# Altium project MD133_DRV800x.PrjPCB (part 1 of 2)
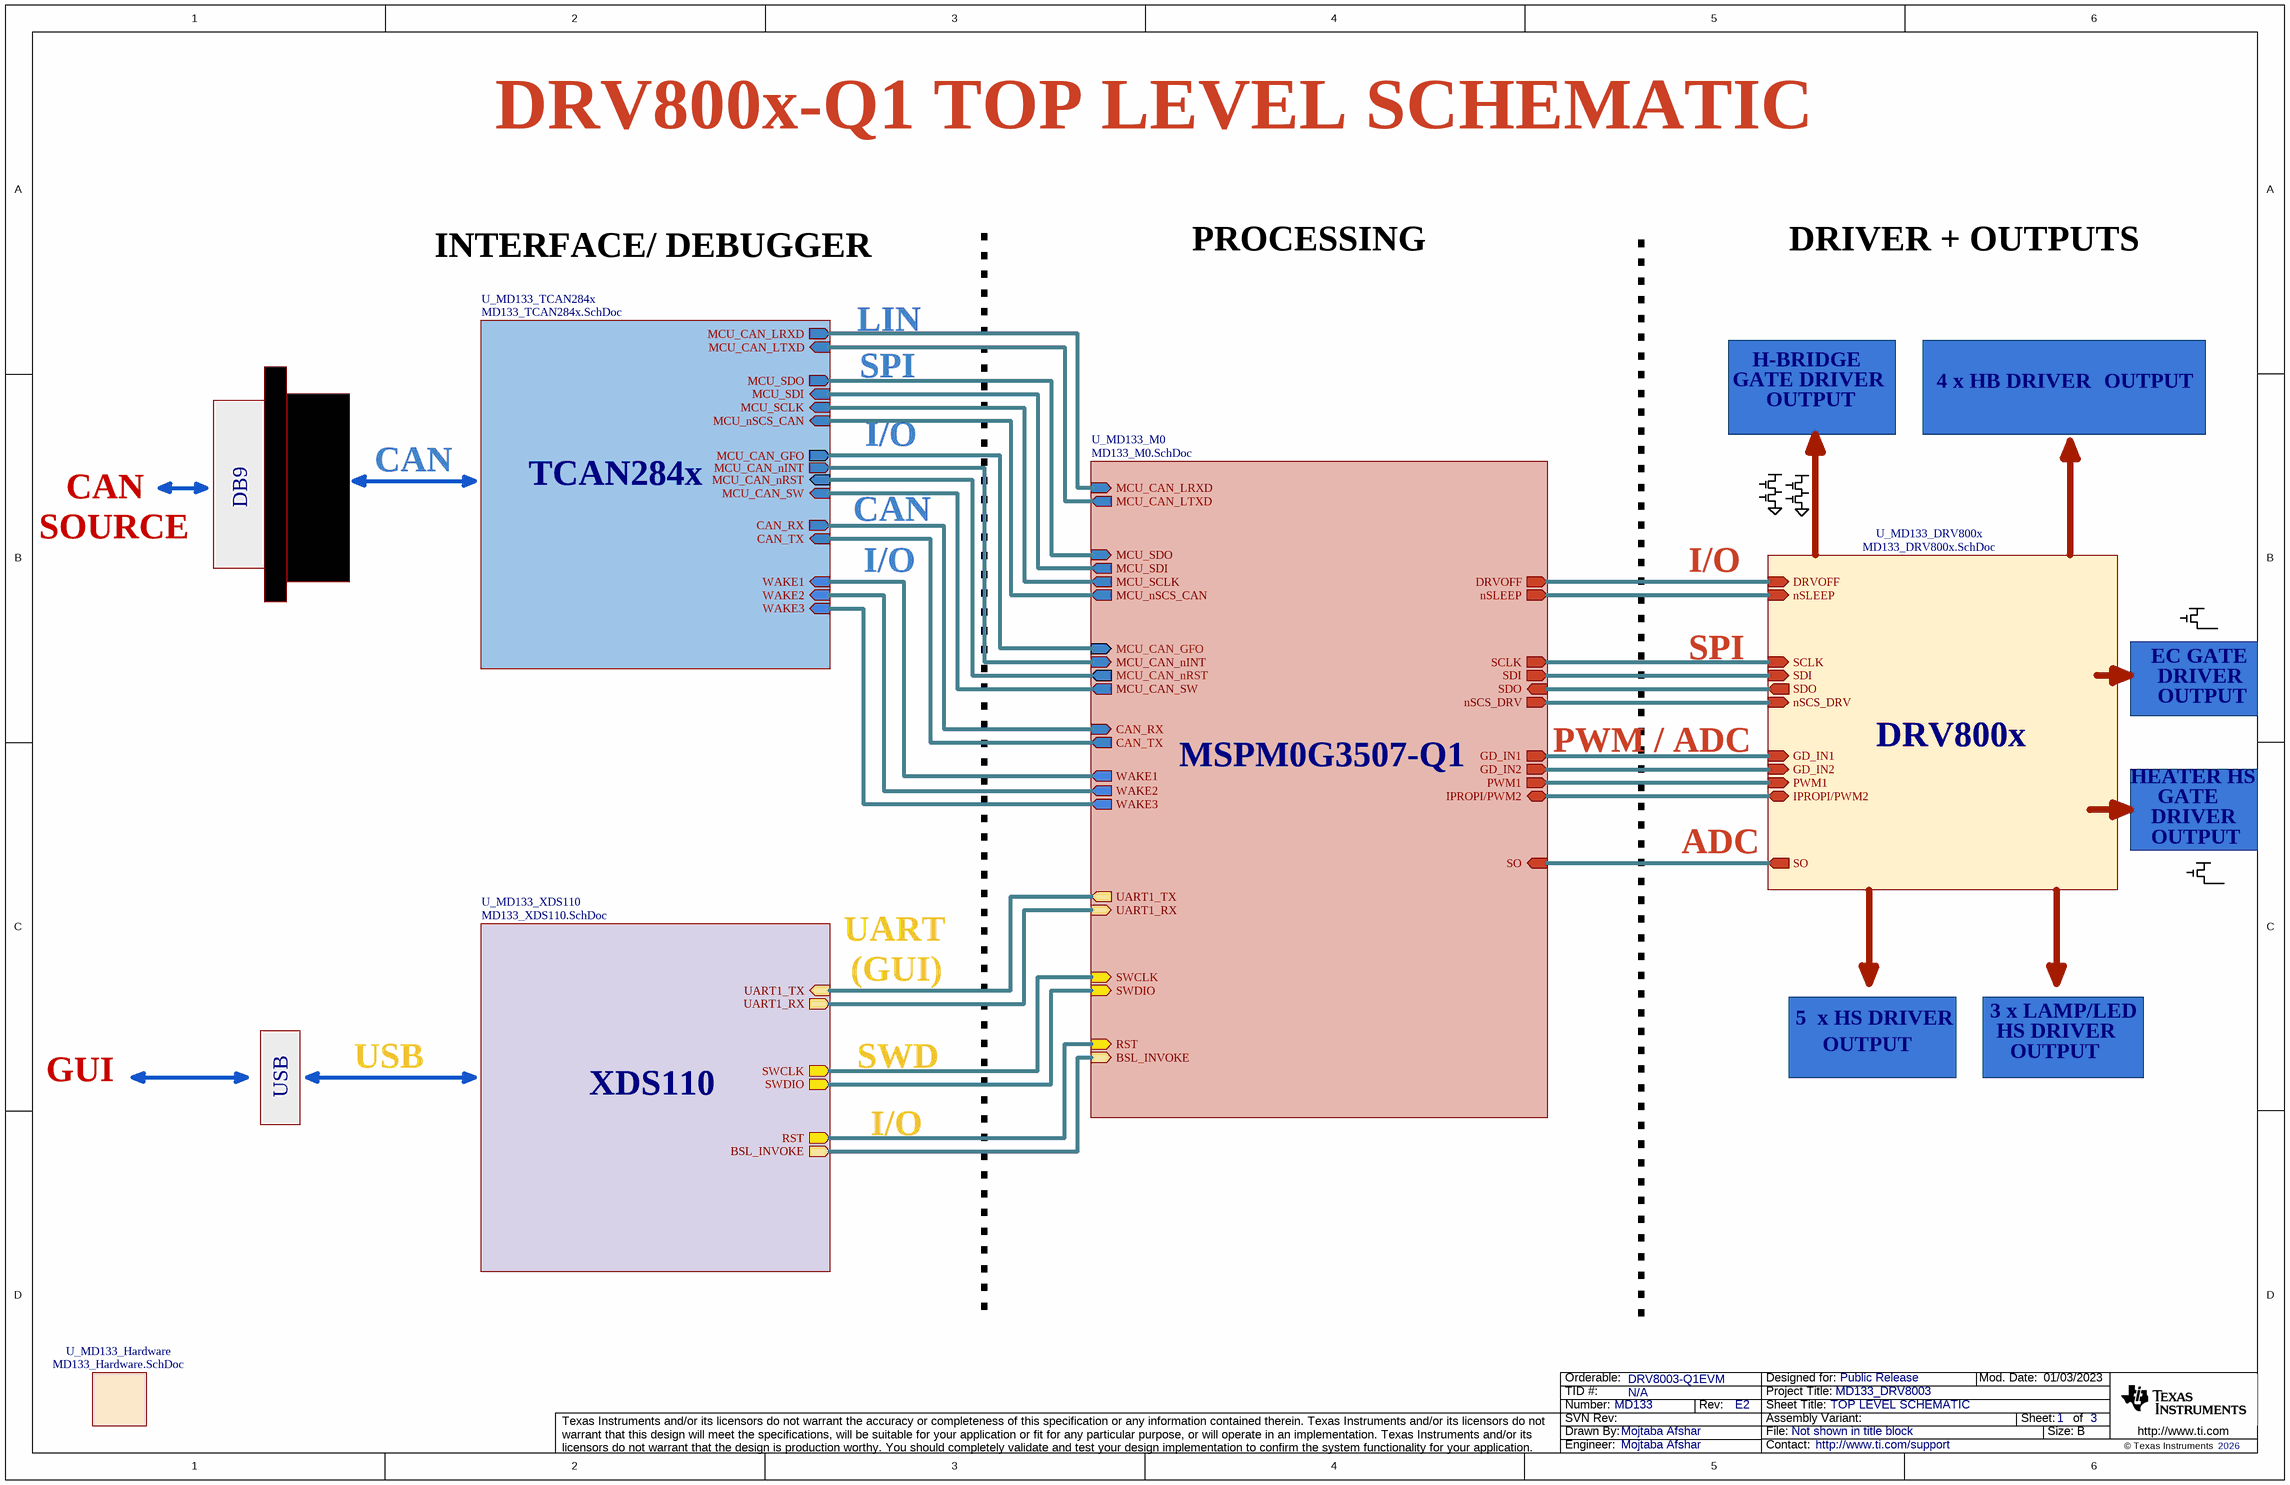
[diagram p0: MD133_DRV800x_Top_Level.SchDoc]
TID: N/A; TechSupport: http://www.ti.com/support; SCH_Rev: E2; PRJ_Title: MD133_DRV8003; PRJ_Number: MD133; PRJ_Engineer: Mojtaba Afshar; PRJ_Customer: Public Release; PCB_Rev: E2; PCB_Layout: Mojtaba Afshar; EVM_Orderable: DRV8003-Q1EVM; CopyrightYear: 2026
7 sheets, 317 parts. Net scope: flat (ports and power ports of the same name join across sheets).
Board file: MD133_DRV800x.PcbDoc
Sheets:
  MD133_DRV800x_Top_Level.SchDoc
    U_MD133_Hardware = MD133_Hardware.SchDoc
    U_MD133_XDS110 = MD133_XDS110.SchDoc
    U_MD133_M0 = MD133_M0.SchDoc
    U_MD133_TCAN284x = MD133_TCAN284x.SchDoc
    U_MD133_DRV800x = MD133_DRV800x.SchDoc
  Sheet1.SchDoc

## Sheet MD133_DRV800x_Top_Level.SchDoc: TOP LEVEL SCHEMATIC
size 431 x 279 mm; Date: Not shown in title block; ApprovedBy: Not shown in title block; CheckedBy: Not shown in title block; Author: Not shown in title block; CompanyName: Not shown in title block; DrawnBy: Mojtaba Afshar; Engineer: Not shown in title block; Organization: Not shown in title block; Address1: Not shown in title block; Address2: Not shown in title block; Address3: Not shown in title block; Address4: Not shown in title block; DocumentNumber: 2; Revision: Use project parameter SCH_Rev; SheetNumber: 1; SheetTotal: 3; PageSetup: Record=PageOptions¦CenterHorizontal=True¦CenterVertical=True¦PrintScale=1.00¦XCorrection=1.00¦YCorrection=1.00¦PrintKind=0¦BorderSize=5000000¦LeftOffset=0¦BottomOffset=0¦Orientation=2¦PaperLength=1000¦PaperWidth=1000¦Scale=100¦PaperSource=15¦PrintQuality=600¦MediaType=1¦DitherType=10¦PaperKind=Letter¦PrintScaleMode=1

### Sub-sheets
U_MD133_DRV800x = MD133_DRV800x.SchDoc: GD_IN1 (in), GD_IN2 (in), PWM1 (in), SDI (in), SDO (out), SCLK (in), IPROPI/PWM2 (bidir), DRVOFF (in), nSLEEP (in), SO (out), nSCS_DRV (in)
U_MD133_Hardware = MD133_Hardware.SchDoc: no entries
U_MD133_M0 = MD133_M0.SchDoc: SWDIO (in), SWCLK (in), GD_IN1 (out), GD_IN2 (out), PWM1 (out), SDI (out), SDO (in), SCLK (out), IPROPI/PWM2 (bidir), DRVOFF (out), nSLEEP (out), CAN_TX (out), CAN_RX (in), SO (in), RST (in), MCU_CAN_GFO (in), MCU_CAN_nRST (out), MCU_CAN_LTXD (out), MCU_CAN_LRXD (in), MCU_nSCS_CAN (out), MCU_SDO (in), MCU_SDI (out), MCU_SCLK (out), nSCS_DRV (out), MCU_CAN_SW (out), MCU_CAN_nINT (in), UART1_TX (out), UART1_RX (in), BSL_INVOKE (in), WAKE1 (out), WAKE2 (out), WAKE3 (out)
U_MD133_TCAN284x = MD133_TCAN284x.SchDoc: CAN_TX (in), CAN_RX (out), MCU_CAN_GFO (out), MCU_CAN_nRST (in), MCU_CAN_LTXD (in), MCU_CAN_LRXD (out), MCU_nSCS_CAN (in), MCU_SDO (out), MCU_SDI (in), MCU_SCLK (in), MCU_CAN_SW (in), MCU_CAN_nINT (out), WAKE1 (in), WAKE2 (in), WAKE3 (in)
U_MD133_XDS110 = MD133_XDS110.SchDoc: SWDIO (out), SWCLK (out), RST (out), UART1_RX (out), UART1_TX (in), BSL_INVOKE (out)

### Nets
(unnamed): sheet U_MD133_XDS110/SWDIO, sheet U_MD133_M0/SWDIO
(unnamed): sheet U_MD133_XDS110/SWCLK, sheet U_MD133_M0/SWCLK  [a separate net that carries the same name]
(unnamed): sheet U_MD133_XDS110/RST, sheet U_MD133_M0/RST  [a separate net that carries the same name]
(unnamed): sheet U_MD133_XDS110/UART1_RX, sheet U_MD133_M0/UART1_RX  [a separate net that carries the same name]
(unnamed): sheet U_MD133_XDS110/UART1_TX, sheet U_MD133_M0/UART1_TX  [a separate net that carries the same name]
(unnamed): sheet U_MD133_XDS110/BSL_INVOKE, sheet U_MD133_M0/BSL_INVOKE  [a separate net that carries the same name]
(unnamed): sheet U_MD133_M0/GD_IN1, sheet U_MD133_DRV800x/GD_IN1  [a separate net that carries the same name]
(unnamed): sheet U_MD133_M0/GD_IN2, sheet U_MD133_DRV800x/GD_IN2  [a separate net that carries the same name]
(unnamed): sheet U_MD133_M0/PWM1, sheet U_MD133_DRV800x/PWM1  [a separate net that carries the same name]
(unnamed): sheet U_MD133_M0/SDI, sheet U_MD133_DRV800x/SDI  [a separate net that carries the same name]
(unnamed): sheet U_MD133_M0/SDO, sheet U_MD133_DRV800x/SDO  [a separate net that carries the same name]
(unnamed): sheet U_MD133_M0/SCLK, sheet U_MD133_DRV800x/SCLK  [a separate net that carries the same name]
(unnamed): sheet U_MD133_M0/IPROPI/PWM2, sheet U_MD133_DRV800x/IPROPI/PWM2  [a separate net that carries the same name]
(unnamed): sheet U_MD133_M0/DRVOFF, sheet U_MD133_DRV800x/DRVOFF  [a separate net that carries the same name]
(unnamed): sheet U_MD133_M0/nSLEEP, sheet U_MD133_DRV800x/nSLEEP  [a separate net that carries the same name]
(unnamed): sheet U_MD133_M0/CAN_TX, sheet U_MD133_TCAN284x/CAN_TX  [a separate net that carries the same name]
(unnamed): sheet U_MD133_M0/CAN_RX, sheet U_MD133_TCAN284x/CAN_RX  [a separate net that carries the same name]
(unnamed): sheet U_MD133_M0/SO, sheet U_MD133_DRV800x/SO  [a separate net that carries the same name]
(unnamed): sheet U_MD133_M0/MCU_CAN_GFO, sheet U_MD133_TCAN284x/MCU_CAN_GFO  [a separate net that carries the same name]
(unnamed): sheet U_MD133_M0/MCU_CAN_nRST, sheet U_MD133_TCAN284x/MCU_CAN_nRST  [a separate net that carries the same name]
(unnamed): sheet U_MD133_M0/MCU_CAN_LTXD, sheet U_MD133_TCAN284x/MCU_CAN_LTXD  [a separate net that carries the same name]
(unnamed): sheet U_MD133_M0/MCU_CAN_LRXD, sheet U_MD133_TCAN284x/MCU_CAN_LRXD  [a separate net that carries the same name]
(unnamed): sheet U_MD133_M0/MCU_nSCS_CAN, sheet U_MD133_TCAN284x/MCU_nSCS_CAN  [a separate net that carries the same name]
(unnamed): sheet U_MD133_M0/MCU_SDO, sheet U_MD133_TCAN284x/MCU_SDO  [a separate net that carries the same name]
(unnamed): sheet U_MD133_M0/MCU_SDI, sheet U_MD133_TCAN284x/MCU_SDI  [a separate net that carries the same name]
(unnamed): sheet U_MD133_M0/MCU_SCLK, sheet U_MD133_TCAN284x/MCU_SCLK  [a separate net that carries the same name]
(unnamed): sheet U_MD133_M0/nSCS_DRV, sheet U_MD133_DRV800x/nSCS_DRV  [a separate net that carries the same name]
(unnamed): sheet U_MD133_M0/MCU_CAN_SW, sheet U_MD133_TCAN284x/MCU_CAN_SW  [a separate net that carries the same name]
(unnamed): sheet U_MD133_M0/MCU_CAN_nINT, sheet U_MD133_TCAN284x/MCU_CAN_nINT  [a separate net that carries the same name]
(unnamed): sheet U_MD133_M0/WAKE1, sheet U_MD133_TCAN284x/WAKE1  [a separate net that carries the same name]
(unnamed): sheet U_MD133_M0/WAKE2, sheet U_MD133_TCAN284x/WAKE2  [a separate net that carries the same name]
(unnamed): sheet U_MD133_M0/WAKE3, sheet U_MD133_TCAN284x/WAKE3  [a separate net that carries the same name]

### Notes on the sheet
- DRV800x-Q1 TOP LEVEL SCHEMATIC
- INTERFACE/ DEBUGGER
- PROCESSING
- DRIVER + OUTPUTS
- LIN
- H-BRIDGE
- SPI
- GATE DRIVER
- OUTPUT
- 4 x HB DRIVER
- CAN
- TCAN284x
- I/O
- SOURCE
- DB9
- EC GATE
- DRIVER
- PWM / ADC
- DRV800x
- MSPM0G3507-Q1
- HEATER HS
- GATE
- ADC
- UART
- (GUI)
- 5  x HS DRIVER
- 3 x LAMP/LED
- GUI
- USB
- XDS110
- SWD
- HS DRIVER

## Sheet MD133_Hardware.SchDoc: HARDWARE
size 431 x 279 mm; Date: Not shown in title block; ApprovedBy: Not shown in title block; CheckedBy: Not shown in title block; Author: Not shown in title block; CompanyName: Not shown in title block; DrawnBy: Mojtaba Afshar; Engineer: Not shown in title block; Organization: Not shown in title block; Address1: Not shown in title block; Address2: Not shown in title block; Address3: Not shown in title block; Address4: Not shown in title block; DocumentNumber: 3; Revision: Use project parameter SCH_Rev; SheetNumber: 6; SheetTotal: 2; PageSetup: Record=PageOptions¦CenterHorizontal=True¦CenterVertical=True¦PrintScale=1.00¦XCorrection=1.00¦YCorrection=1.00¦PrintKind=0¦BorderSize=5000000¦LeftOffset=0¦BottomOffset=0¦Orientation=2¦PaperLength=1000¦PaperWidth=1000¦Scale=100¦PaperSource=15¦PrintQuality=600¦MediaType=1¦DitherType=10¦PaperKind=Letter¦PrintScaleMode=1
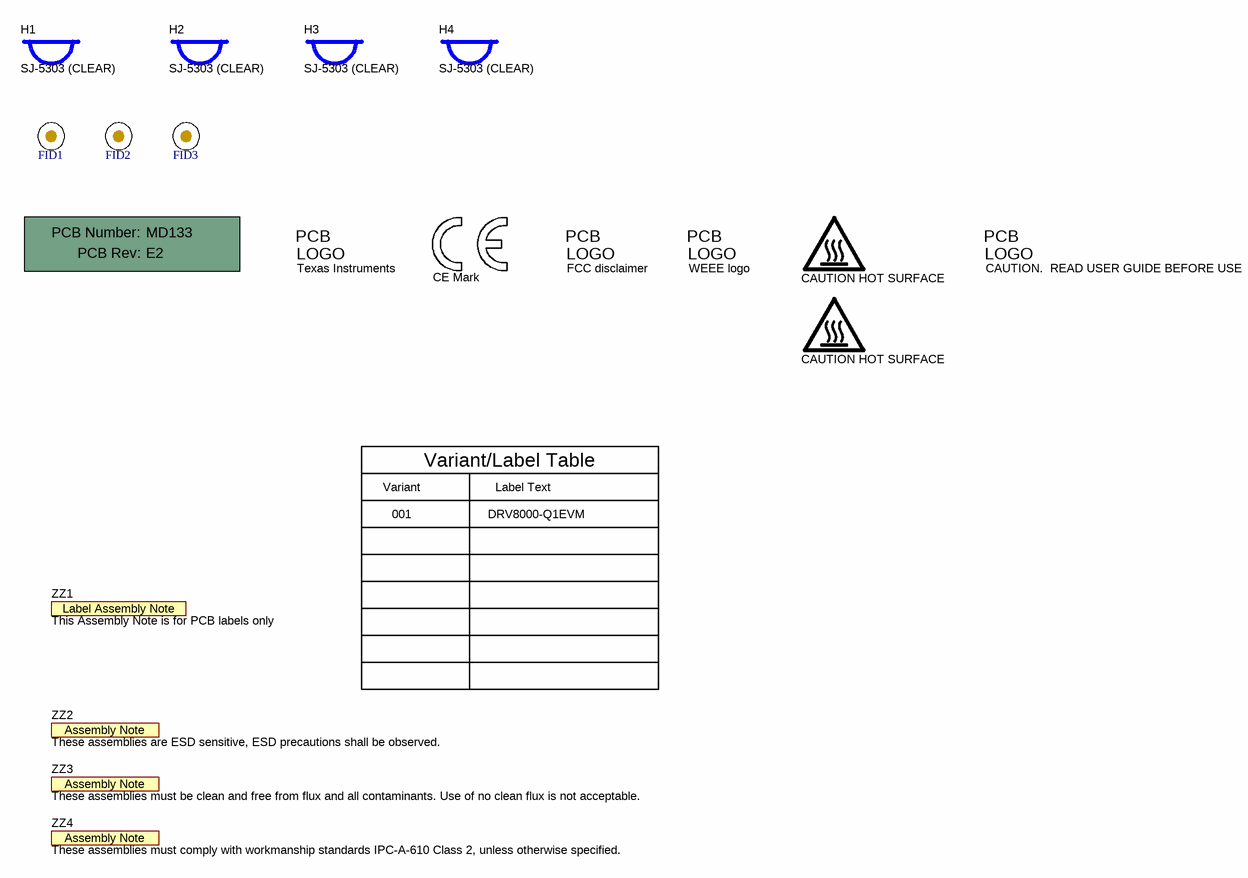
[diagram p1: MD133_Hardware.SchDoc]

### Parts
!PCB1  Printed Circuit Board  (value not drawn)  (mechanical)
FID1  Fiducial  [Fiducial10-20]  (value not drawn)
FID2  Fiducial  [Fiducial10-20]  (value not drawn)
FID3  Fiducial  [Fiducial10-20]  (value not drawn)
H1  SJ-5303 (CLEAR)  [Bumpon_SJ5003Transparent]
H2  SJ-5303 (CLEAR)  [Bumpon_SJ5003Transparent]
H3  SJ-5303 (CLEAR)  [Bumpon_SJ5003Transparent]
H4  SJ-5303 (CLEAR)  [Bumpon_SJ5003Transparent]
Logo1  CE Mark  [CE_Mark_5mm]  (no BOM)
Logo2  Texas Instruments  [TI_Stacked_Overlay_Small]  (no BOM)
Logo3  FCC disclaimer  [FCC_disclaimer]  (no BOM)
Logo4  WEEE logo  [WEEE_Minimum]  (no BOM)
LOGO5  CAUTION HOT SURFACE  [IEC_HotSurface_Small]  (no BOM)
Logo6  CAUTION.  READ USER GUIDE BEFORE USE  [IEC_Caution_Small]  (no BOM)
LOGO7  CAUTION HOT SURFACE  [IEC_HotSurface_Small]  (no BOM)
ZZ1  This Assembly Note is for PCB labels only  [AssemblyNoteLabel]  (no BOM)
ZZ2  These assemblies are ESD sensitive, ESD precautions shall be observed.  [AssemblyNote]  (no BOM)
ZZ3  These assemblies must be clean and free from flux and all contaminants. Use of no clean flux is not acceptable.  [AssemblyNote]  (no BOM)
ZZ4  These assemblies must comply with workmanship standards IPC-A-610 Class 2, unless otherwise specified.  [AssemblyNote]  (no BOM)

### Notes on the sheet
- Variant
- Variant/Label Table
- Label Text
- 001
- DRV8000-Q1EVM

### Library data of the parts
!PCB1 = CMP-0003618-2: Manufacturer: Any; PartNumber: MD133
FID1-FID3 = CMP-0077181-1: Fiducial mark.  There is nothing to buy or mount.
H1-H4 = CMP-0003620-1: Bumpon, Hemisphere, 0.44 X 0.20, Clear; Manufacturer: 3M
Logo1 = CMP-0074844-1: SymbolCreator: a0412235
Logo2 = CMP-0074838-1: Texas Instrument Corporate Signature; SymbolCreator: a0412235; Lib Reference: TI_Logo
Logo3 = CMP-0074847-1: FCC_disclaimer
Logo4 = CMP-0074769-3: Manufacturer: Texas Instruments; AEC Category: Q200; CompType: IC
LOGO5 LOGO7 = CMP-0074837-2: IEC 61010-1 Hot Surface Warning; Manufacturer: Texas Instruments; SymbolCreator: a0412235; CompType: IC; AEC Category: Q200
Logo6 = CMP-0074836-1: IEC 61010-1 Caution Warning; SymbolCreator: a0412235; Lib Reference: IEC_Caution
ZZ1 = CMP-0003616-3
ZZ2 = CMP-0077236-1
ZZ3 = CMP-0077237-1
ZZ4 = CMP-0077238-1

## Sheet MD133_XDS110.SchDoc: XDS110
size 431 x 279 mm; Date: Not shown in title block; ApprovedBy: Not shown in title block; CheckedBy: Not shown in title block; Author: Not shown in title block; CompanyName: Not shown in title block; DrawnBy: Mojtaba Afshar; Engineer: Not shown in title block; Organization: Not shown in title block; Address1: Not shown in title block; Address2: Not shown in title block; Address3: Not shown in title block; Address4: Not shown in title block; DocumentNumber: 2; Revision: Use project parameter SCH_Rev; SheetNumber: 2; SheetTotal: 2; PageSetup: Record=PageOptions¦CenterHorizontal=True¦CenterVertical=True¦PrintScale=1.00¦XCorrection=1.00¦YCorrection=1.00¦PrintKind=0¦BorderSize=5000000¦LeftOffset=0¦BottomOffset=0¦Orientation=2¦PaperLength=1000¦PaperWidth=1000¦Scale=100¦PaperSource=15¦PrintQuality=600¦MediaType=1¦DitherType=10¦PaperKind=Letter¦PrintScaleMode=1
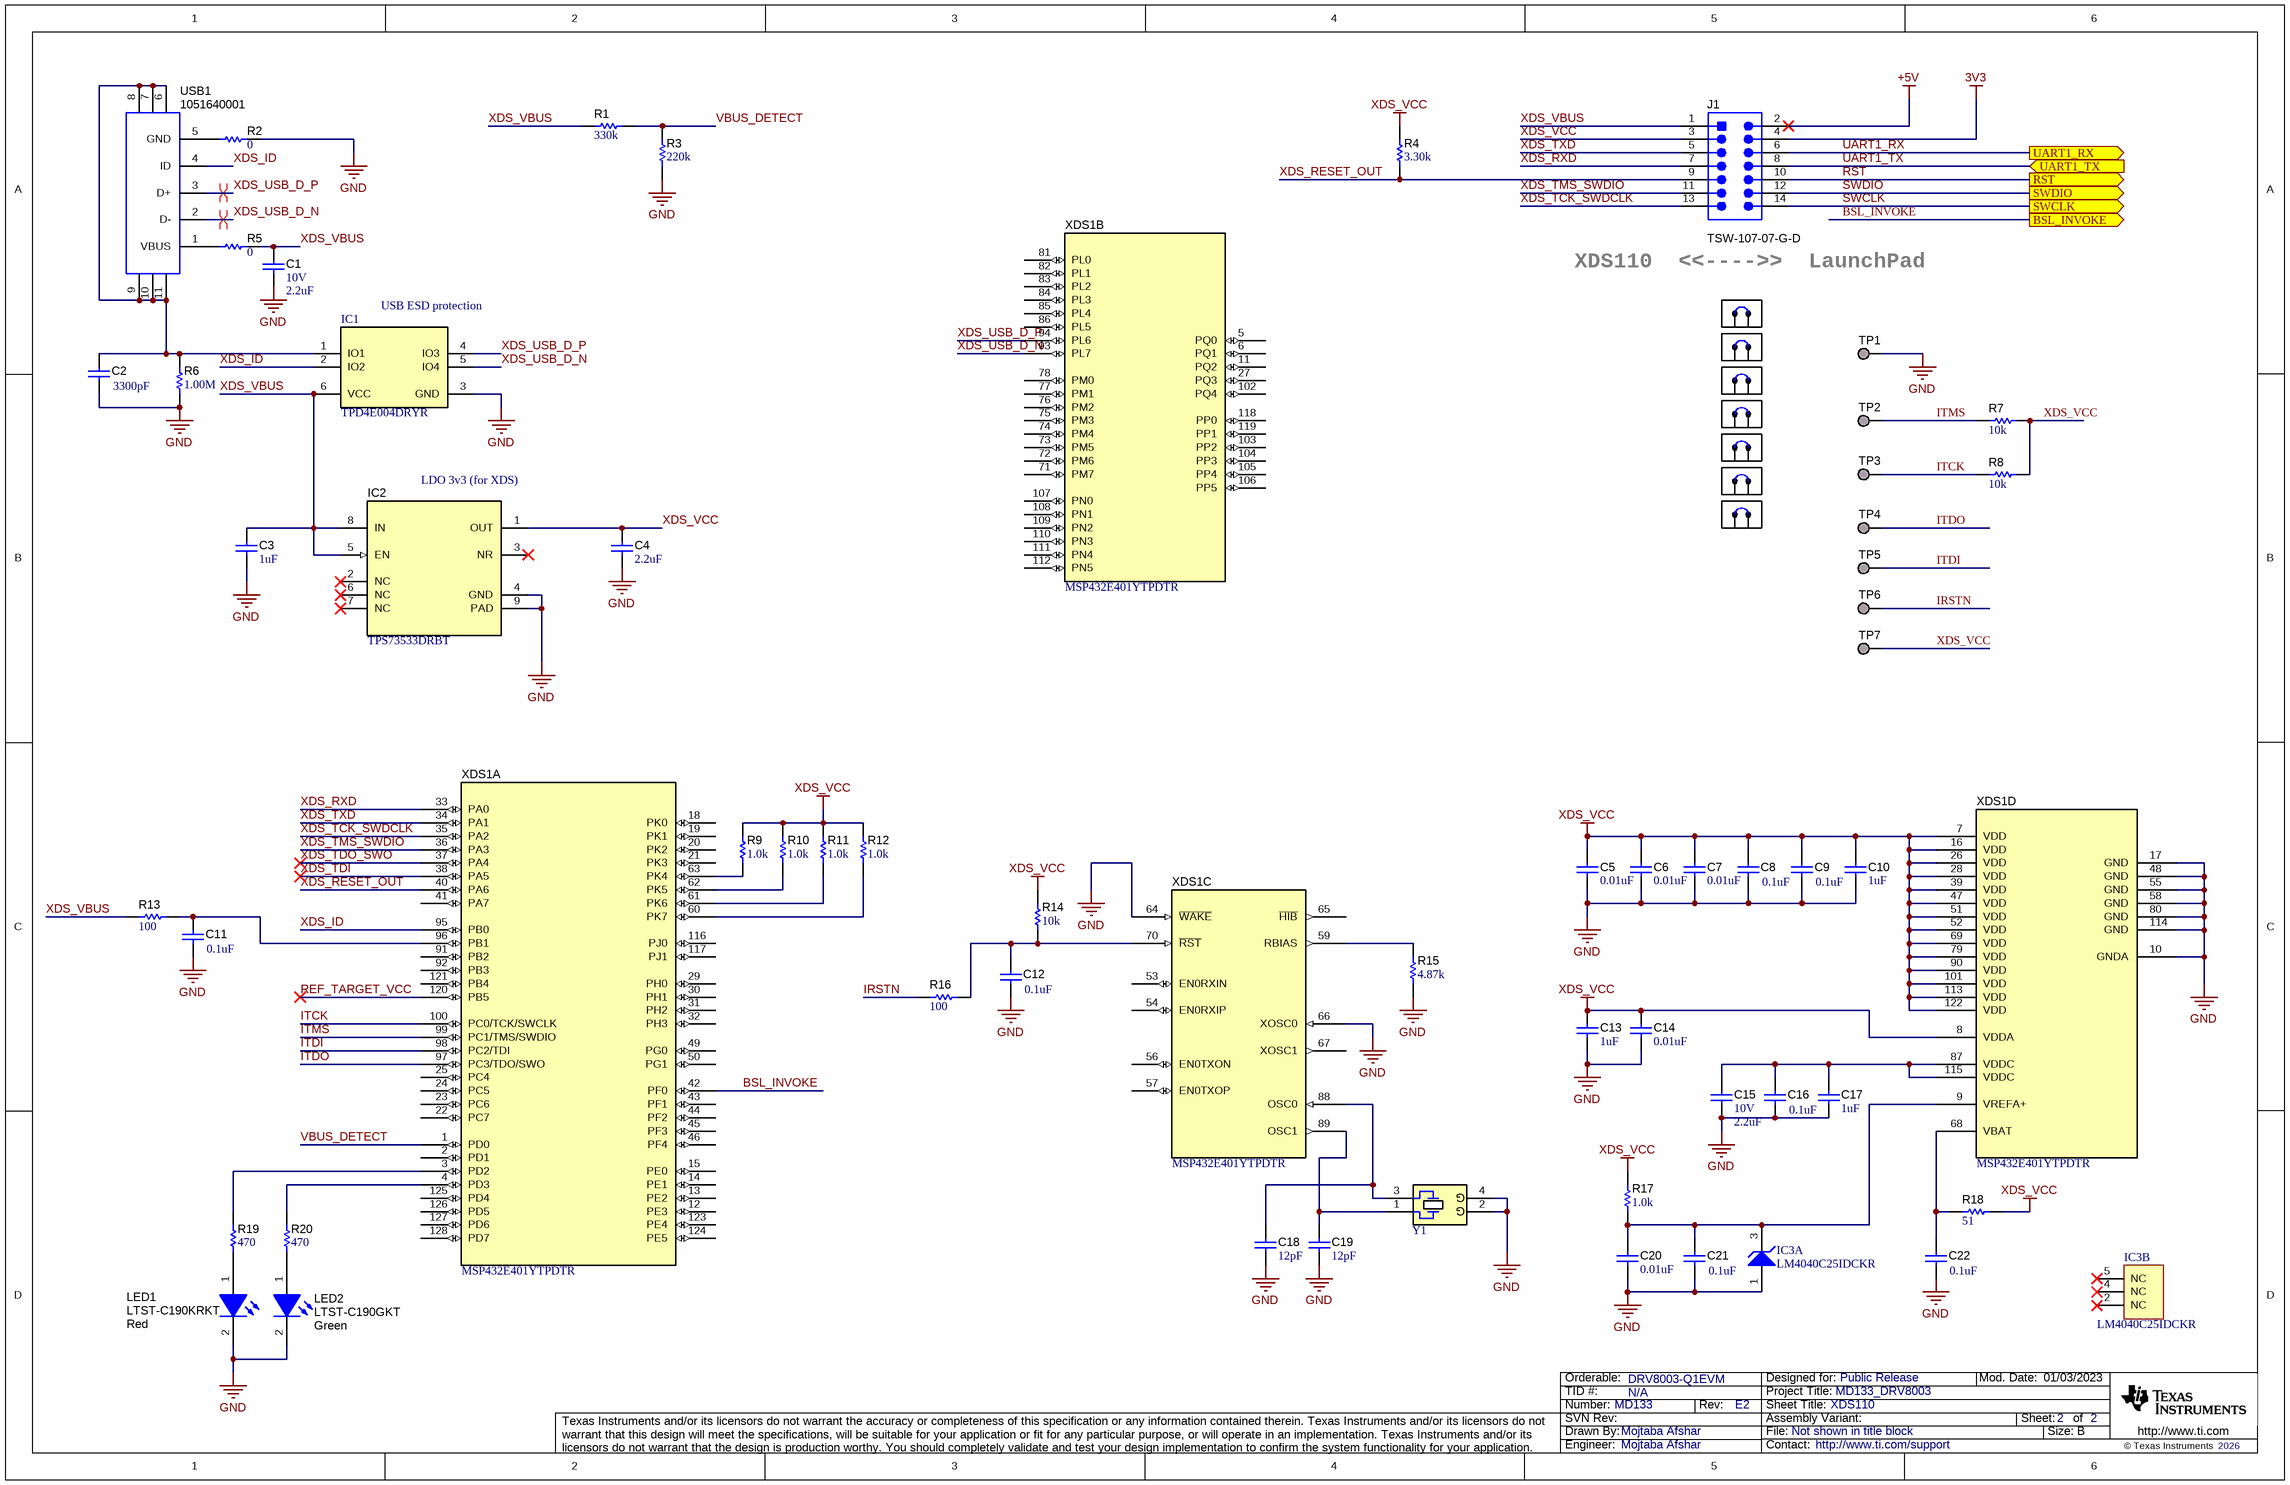
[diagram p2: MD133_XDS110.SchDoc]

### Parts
C1  VDC_V: 10V  ValueDisplayed: 2.2uF  [0603]  (hidden comment: C0603C225K8PACTU)
C2  ValueDisplayed: 3300pF  [0402]  (hidden comment: GRM155R71H332KA01D)
C3  ValueDisplayed: 1uF  [0402]  (hidden comment: C1005X5R1E105K050BC)
C4  ValueDisplayed: 2.2uF  [0402]  (hidden comment: CL05A225KQ5NNNC)
C5  ValueDisplayed: 0.01uF  [0402]  (hidden comment: GRM155R71E103KA01D)
C6  ValueDisplayed: 0.01uF  [0402]  (hidden comment: GRM155R71E103KA01D)
C7  ValueDisplayed: 0.01uF  [0402]  (hidden comment: GRM155R71E103KA01D)
C8  ValueDisplayed: 0.1uF  [0402]  (hidden comment: GRM155R70J104KA01D)
C9  ValueDisplayed: 0.1uF  [0402]  (hidden comment: GRM155R70J104KA01D)
C10  ValueDisplayed: 1uF  [0402]  (hidden comment: C1005X5R1E105K050BC)
C11  ValueDisplayed: 0.1uF  [0402]  (hidden comment: GRM155R70J104KA01D)
C12  ValueDisplayed: 0.1uF  [0402]  (hidden comment: GRM155R70J104KA01D)
C13  ValueDisplayed: 1uF  [0402]  (hidden comment: C1005X5R1E105K050BC)
C14  ValueDisplayed: 0.01uF  [0402]  (hidden comment: GRM155R71E103KA01D)
C15  VDC_V: 10V  ValueDisplayed: 2.2uF  [0603]  (hidden comment: C0603C225K8PACTU)
C16  ValueDisplayed: 0.1uF  [0402]  (hidden comment: GRM155R70J104KA01D)
C17  ValueDisplayed: 1uF  [0402]  (hidden comment: C1005X5R1E105K050BC)
C18  ValueDisplayed: 12pF  [0402]  (hidden comment: GRM1555C1H120JA01D)
C19  ValueDisplayed: 12pF  [0402]  (hidden comment: GRM1555C1H120JA01D)
C20  ValueDisplayed: 0.01uF  [0402]  (hidden comment: GRM155R71E103KA01D)
C21  ValueDisplayed: 0.1uF  [0402]  (hidden comment: GRM155R70J104KA01D)
C22  ValueDisplayed: 0.1uF  [0402]  (hidden comment: GRM155R70J104KA01D)
IC1  TPD4E004DRYR  [DRY0006A]
IC2  TPS73533DRBT  [DRB0008A]
IC3  LM4040C25IDCKR  [DCK0005A_N]  (parts A,B of 2)
J1  TSW-107-07-G-D  [TSW-107-07-X-D]
LED1  LTST-C190KRKT  value Red  [LED_LTST-C190_Red]
LED2  LTST-C190GKT  value Green  [LED_LTST-C190]
R1  ValueDisplayed: 330k  [0402]  (hidden comment: RC0402FR-07330KL)
R2  ValueDisplayed: 0  [0603]  (hidden comment: RC0603JR-070RL)
R3  ValueDisplayed: 220k  [0402]  (hidden comment: RC0402FR-07220KL)
R4  ValueDisplayed: 3.30k  [0402]  (hidden comment: ERJ-2RKF3301X)
R5  ValueDisplayed: 0  [0603]  (hidden comment: RC0603JR-070RL)
R6  ValueDisplayed: 1.00M  [0402]  (hidden comment: CRCW04021M00FKED)
R7  ValueDisplayed: 10k  [0402]  (hidden comment: CRCW040210K0JNED)
R8  ValueDisplayed: 10k  [0402]  (hidden comment: CRCW040210K0JNED)
R9  ValueDisplayed: 1.0k  [0402]  (hidden comment: CRCW04021K00JNED)
R10  ValueDisplayed: 1.0k  [0402]  (hidden comment: CRCW04021K00JNED)
R11  ValueDisplayed: 1.0k  [0402]  (hidden comment: CRCW04021K00JNED)
R12  ValueDisplayed: 1.0k  [0402]  (hidden comment: CRCW04021K00JNED)
R13  ValueDisplayed: 100  [0402]  (hidden comment: CRCW0402100RJNED)
R14  ValueDisplayed: 10k  [0402]  (hidden comment: CRCW040210K0JNED)
R15  ValueDisplayed: 4.87k  [0402]  (hidden comment: CRCW04024K87FKED)
R16  ValueDisplayed: 100  [0402]  (hidden comment: CRCW0402100RJNED)
R17  ValueDisplayed: 1.0k  [0402]  (hidden comment: CRCW04021K00JNED)
R18  ValueDisplayed: 51  [0402]  (hidden comment: CRCW040251R0JNED)
R19  ValueDisplayed: 470  [0402]  (hidden comment: CRCW0402470RJNED)
R20  ValueDisplayed: 470  [0402]  (hidden comment: CRCW0402470RJNED)
SH-J14  60900213421  [Wurth_60900213421]  (value not drawn)
SH-J15  60900213421  [Wurth_60900213421]  (value not drawn)
SH-J16  60900213421  [Wurth_60900213421]  (value not drawn)
SH-J17  60900213421  [Wurth_60900213421]  (value not drawn)
SH-J18  60900213421  [Wurth_60900213421]  (value not drawn)
SH-J19  60900213421  [Wurth_60900213421]  (value not drawn)
SH-J20  60900213421  [Wurth_60900213421]  (value not drawn)
TP1  TESTPOINT  [TP_SM_1MM]  (value not drawn)  (no BOM)
TP2  TESTPOINT  [TP_SM_1MM]  (value not drawn)  (no BOM)
TP3  TESTPOINT  [TP_SM_1MM]  (value not drawn)  (no BOM)
TP4  TESTPOINT  [TP_SM_1MM]  (value not drawn)  (no BOM)
TP5  TESTPOINT  [TP_SM_1MM]  (value not drawn)  (no BOM)
TP6  TESTPOINT  [TP_SM_1MM]  (value not drawn)  (no BOM)
TP7  TESTPOINT  [TP_SM_1MM]  (value not drawn)  (no BOM)
USB1  1051640001  [Molex_1051640001]
XDS1  MSP432E401YTPDTR  [PDT0128A]  (parts A,B,C,D of 4)
Y1  NX3225GA-16.000M-STD-CRG-1  [NDK_NX3225GA]  (value not drawn)

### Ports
BSL_INVOKE (out), RST (out), SWCLK (out), SWDIO (out), UART1_RX (out), UART1_TX (in)

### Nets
3V3: J1.4
+5V: J1.2
GND: C1.2 C2.2 C3.2 C4.2 C5.2 C6.2 C7.2 C8.2 C9.2 C10.2 C11.2 C12.2 C13.2 C14.2 C15.2 C16.2 C17.2 C18.2 C19.2 C20.2 C21.2 C22.2 IC1.3(GND) IC2.4(GND) IC2.9(PAD) IC3.1(ANODE) LED1.2(K) LED2.2(K) R2.2 R3.1 R6.1 R15.1 TP1.1 XDS1.10(GNDA) XDS1.17(GND) XDS1.48(GND) XDS1.55(GND) XDS1.58(GND) XDS1.64(~{WAKE}) XDS1.66(XOSC0) XDS1.80(GND) XDS1.114(GND) Y1.2(GND) Y1.4(GND)
XDS_VCC: C4.1 C5.1 C6.1 C7.1 C8.1 C9.1 C10.1 C13.1 C14.1 IC2.1(OUT) J1.3 R4.2 R7.1 R8.1 R9.2 R10.2 R11.2 R12.2 R14.2 R17.2 R18.2 TP7.1 XDS1.7(VDD) XDS1.8(VDDA) XDS1.16(VDD) XDS1.26(VDD) XDS1.28(VDD) XDS1.39(VDD) XDS1.47(VDD) XDS1.51(VDD) XDS1.52(VDD) XDS1.69(VDD) XDS1.79(VDD) XDS1.90(VDD) XDS1.101(VDD) XDS1.113(VDD) XDS1.122(VDD)
BSL_INVOKE: XDS1.42(PF0) ; port BSL_INVOKE
IRSTN: R16.1 TP6.1
ITCK: R8.2 TP3.1 XDS1.100(PC0/TCK/SWCLK)
ITDI: TP5.1 XDS1.98(PC2/TDI)
ITDO: TP4.1 XDS1.97(PC3/TDO/SWO)
ITMS: R7.2 TP2.1 XDS1.99(PC1/TMS/SWDIO)
REF_TARGET_VCC: XDS1.120(PB5)
RST: J1.10 ; port RST
SWCLK: J1.14 ; port SWCLK
SWDIO: J1.12 ; port SWDIO
UART1_RX: J1.6 ; port UART1_RX
UART1_TX: J1.8 ; port UART1_TX
VBUS_DETECT: R1.2 R3.2 XDS1.1(PD0)
XDS_ID: IC1.2(IO2) USB1.4(ID) XDS1.95(PB0)
XDS_RESET_OUT: J1.9 R4.1 XDS1.40(PA6)
XDS_RXD: J1.7 XDS1.33(PA0)
XDS_TCK_SWDCLK: J1.13 XDS1.35(PA2)
XDS_TDI: XDS1.38(PA5)
XDS_TDO_SWO: XDS1.37(PA4)
XDS_TMS_SWDIO: J1.11 XDS1.36(PA3)
XDS_TXD: J1.5 XDS1.34(PA1)
XDS_USB_D_N: IC1.5(IO4) USB1.2(D-) XDS1.93(PL7)
XDS_USB_D_P: IC1.4(IO3) USB1.3(D+) XDS1.94(PL6)
XDS_VBUS: C1.1 C3.1 IC1.6(VCC) IC2.5(EN) IC2.8(IN) J1.1 R1.1 R5.2 R13.1
NetC2_1: C2.1 IC1.1(IO1) R6.2 USB1.6 USB1.7 USB1.8 USB1.9 USB1.10 USB1.11
NetC11_1: C11.1 R13.2 XDS1.96(PB1)
NetC12_1: C12.1 R14.1 R16.2 XDS1.70(~{RST})
NetC15_1: C15.1 C16.1 C17.1 XDS1.87(VDDC) XDS1.115(VDDC)
NetC18_1: C18.1 XDS1.88(OSC0) Y1.3
NetC19_1: C19.1 XDS1.89(OSC1) Y1.1
NetC20_1: C20.1 C21.1 IC3.3(CATHODE) R17.1 XDS1.9(VREFA+)
NetC22_1: C22.1 R18.1 XDS1.68(VBAT)
NetLED1_1: LED1.1(A) R19.1
NetLED2_1: LED2.1(A) R20.1
NetR2_1: R2.1 USB1.5(GND)
NetR5_1: R5.1 USB1.1(VBUS)
NetR9_1: R9.1 XDS1.63(PK4)
NetR10_1: R10.1 XDS1.62(PK5)
NetR11_1: R11.1 XDS1.61(PK6)
NetR12_1: R12.1 XDS1.60(PK7)
NetR15_2: R15.2 XDS1.59(RBIAS)
NetR19_2: R19.2 XDS1.3(PD2)
NetR20_2: R20.2 XDS1.4(PD3)

Not connected (* = marked no-connect by the designer): IC2 2(NC)* 3(NR)* 6(NC)* 7(NC)*; IC3 2(NC)* 4(NC)* 5(NC)*; XDS1 2(PD1) 5(PQ0) 6(PQ1) 11(PQ2) 12(PE3) 13(PE2) 14(PE1) 15(PE0) 18(PK0) 19(PK1) 20(PK2) 21(PK3) 22(PC7) 23(PC6) 24(PC5) 25(PC4) 27(PQ3) 29(PH0) 30(PH1) 31(PH2) 32(PH3) 41(PA7) 43(PF1) 44(PF2) 45(PF3) 46(PF4) 49(PG0) 50(PG1) 53(EN0RXIN) 54(EN0RXIP) 56(EN0TXON) 57(EN0TXOP) 65(~{HIB}) 67(XOSC1) 71(PM7) 72(PM6) 73(PM5) 74(PM4) 75(PM3) 76(PM2) 77(PM1) 78(PM0) 81(PL0) 82(PL1) 83(PL2) 84(PL3) 85(PL4) 86(PL5) 91(PB2) 92(PB3) 102(PQ4) 103(PP2) 104(PP3) 105(PP4) 106(PP5) 107(PN0) 108(PN1) 109(PN2) 110(PN3) 111(PN4) 112(PN5) 116(PJ0) 117(PJ1) 118(PP0) 119(PP1) 121(PB4) 123(PE4) 124(PE5) 125(PD4) 126(PD5) 127(PD6) 128(PD7)

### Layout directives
differential pair: XDS_USB_D_N, XDS_USB_D_P

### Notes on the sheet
- XDS110  <<---->>  LaunchPad
- (near IC1) USB ESD protection
- (near IC2) LDO 3v3 (for XDS)

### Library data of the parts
C1 C15 = CMP-0006906-5: CAP, CERM, 2.2 uF, 10 V, +/- 10%, X5R, 0603; Manufacturer: Kemet; TaMin_C: -55°C; Polarized: N; SizeAreaWB_mm2: 4.68; Value1: Unknown; U/M: EA; Value: 2.2uF; TaMax_C: 85°C; SizeZ_mm: 1; SizeX_mm: 1.6; SizeY_mm: 0.8; SizeArea_mm2: 1.28; Cap_F: 2.2µF; AEC Category: Q200
C2 = CMP-0006688-2: CAP, CERM, 3300 pF, 50 V, +/- 10%, X7R, 0402; Manufacturer: MuRata; TaMin_C: -55°C; Polarized: N; SizeAreaWB_mm2: 3; Value1: Unknown; U/M: EA; Value: 3300pF; TaMax_C: 125°C; SizeZ_mm: 0.6; SizeX_mm: 1; SizeY_mm: 0.5; Value2: 50V; Cap_F: 3.3nF; AEC Category: Q200
C3 C10 C13 C17 = CMP-0006276-2: CAP, CERM, 1 uF, 25 V, +/- 10%, X5R, 0402; Manufacturer: TDK; TaMin_C: -55°C; Polarized: N; SizeAreaWB_mm2: 3; Value1: Unknown; U/M: EA; Value: 1uF; TaMax_C: 80°C; SizeZ_mm: 0.6; SizeX_mm: 1; SizeY_mm: 0.5; Value2: 25V; Cap_F: 1µF; AEC Category: Q200
C4 = CMP-0006341-2: CAP, CERM, 2.2 uF, 6.3 V, +/- 10%, X5R, 0402; Manufacturer: Samsung; TaMin_C: -55°C; Polarized: N; SizeAreaWB_mm2: 3; Value1: Unknown; U/M: EA; Value: 2.2uF; TaMax_C: 85°C; SizeZ_mm: 0.6; SizeX_mm: 1; SizeY_mm: 0.5; Value2: 6.3V; Cap_F: 2.2µF; AEC Category: Q200
C5-C7 C14 C20 = CMP-0006658-2: CAP, CERM, 0.01 uF, 25 V, +/- 10%, X7R, 0402; Manufacturer: MuRata; TaMin_C: -55°C; Polarized: N; SizeAreaWB_mm2: 3; Value1: Unknown; U/M: EA; Value: 0.01uF; TaMax_C: 125°C; SizeZ_mm: 0.6; SizeX_mm: 1; SizeY_mm: 0.5; Value2: 25V; Cap_F: 10nF; AEC Category: Q200
C8 C9 C11 C12 C16 C21 C22 = CMP-0006623-2: CAP, CERM, 0.1 uF, 6.3 V, +/- 10%, X7R, 0402; Manufacturer: MuRata; TaMin_C: -55°C; Polarized: N; SizeAreaWB_mm2: 3; Value1: Unknown; U/M: EA; Value: 0.1uF; TaMax_C: 125°C; SizeZ_mm: 0.6; SizeX_mm: 1; SizeY_mm: 0.5; Value2: 6.3V; Cap_F: 100nF; AEC Category: Q200
C18 C19 = CMP-0006415-2: CAP, CERM, 12 pF, 50 V, +/- 5%, C0G/NP0, 0402; Manufacturer: MuRata; TaMin_C: -55°C; Polarized: N; SizeAreaWB_mm2: 3; Value1: Unknown; U/M: EA; Value: 12pF; TaMax_C: 125°C; SizeZ_mm: 0.6; SizeX_mm: 1; SizeY_mm: 0.5; Value2: 50V; AEC Category: Q200
IC1 = CMP-0043115-3: 4-Channel ESD Protection Array for High-Speed Data Interfaces, DRY0006A (USON-6); Manufacturer: Texas Instruments; IO Leakage Current(nA): 1; USB High Speed: TRUE; IO Capacitance(Typ)(pF): 1.6; Eco-Plan: Green (RoHS & no Sb/Br); IEC 61000-4-2 Contact(+/- kV): 8; Breakdown Voltage(Min)(V): 6; IEC 61000-4-2 Air-Gap(+/- kV): 12; AEC Category: Q200; AEC Qualified: N; CompType: IC; Rating: Catalog; SizeArea_mm2: 1.45; SizeAreaWB_mm2: 4.9; SizeX_mm: 1.0; SizeZ_mm: 0.6
IC2 = CMP-0036329-3: 500mA, Adjustable, Low Quiescent Current, Low-Noise, High-PSRR, Single-Output LDO Regulator, DRB0008A (VSON-8); Manufacturer: Texas Instruments; AEC Category: Q200; Vout Adj(Max)(V): 3.3; Vdo(Typ)(mV): 280; SizeY_mm: 3.0; Vin(Max)(V): 6.5; Accuracy(%): 2; Vin(Min)(V): 2.7; SizeAreaWB_mm2: 16.0; SizeZ_mm: 1.0; AEC Qualified: N; SizeArea_mm2: 9.0; Iout(Max)(A): 0.5; Rating: Catalog; Iq(Typ)(mA): 0.04; CompType: IC
IC3 = CMP-0032790-2: Precision Micropower Shunt Voltage Reference, 0.5% accuracy, 2.5 V, 15 ppm / degC, 15 mA, -40 to 85 degC, 5-pin SC70 (DCK), Green (RoHS & no Sb/Br); Manufacturer: Texas Instruments; Min Iz for Regulation(uA): 75; Temp Coeff(Max)(ppm/ degree C): 100; VO(V): 2.5; Temp Coeff(Typ)(ppm/ degree C): 15; Rating: Catalog; Initial Accuracy @ 25/deg C(%): 0.5; AEC Category: Q200; AEC Qualified: N; CompType: IC; SizeAreaWB_mm2: 9.3; SizeArea_mm2: 4.2; SizeX_mm: 2.1; SizeY_mm: 2.0; SizeZ_mm: 1.1
J1 = CMP-0075415-2: Header, 100mil, 7x2, Gold, TH; Manufacturer: Samtec; Green_Lifecycle: Active; Green_REACh: Passed; Cert_CSA: Y; Cert_CULUS: N; Current_A: 6.3A; Gender: Male; Pitch_mm: 2.54; Row_Count: 2; Voltage_V: 550V
LED1 = CMP-0078131-2: LED, Red, SMD; Manufacturer: Lite-On; Type: AlInGaP; Ir_A: 10µA; Angle: 130; Power_TotalModule: 62.5mW; Value2: 2V; Green_Lifecycle: Not Set; Io_A: 20mA; Value1: .0625W; Green_REACh: Incomplete; Vr_V: 5V
LED2 = CMP-0002827-3: LED, Green, SMD; Manufacturer: Lite-On; Power_TotalModule: 100mW; Value2: 2.1V; Io_A: 20mA; Value1: 0.1W
R1 = CMP-0026731-1: RES, 330 k, 1%, 0.0625 W, 0402; Manufacturer: Yageo America; Power_W: 62.5mW; TempCo: 100 ppm/C; U/M: EA; Value: 330k; SizeX_mm: 1; SizeY_mm: 0.5; SizeZ_mm: 0.6; AEC Qualified: N; VDC_V: 50V; AEC Category: Q200
R2 R5 = CMP-0025885-5: RES, 0, 5%, 0.1 W, 0603; Manufacturer: Yageo; Power_W: 100mW; TempCo: 200 ppm/C; Value_Code: 0000; Value: 0; EIA_Code: E24; SizeX_mm: 1.6; SizeZ_mm: 1; Value2: 0.1W; SizeArea_mm2: 1.28; AEC Qualified: N; VDC_V: 75V; AEC Category: Q200; SizeY_mm: 0.8; SizeAreaWB_mm2: 4.68
R3 = CMP-0026728-1: RES, 220 k, 1%, 0.0625 W, 0402; Manufacturer: Yageo America; Power_W: 62.5mW; TempCo: 100 ppm/C; U/M: EA; Value: 220k; SizeX_mm: 1; SizeY_mm: 0.5; SizeZ_mm: 0.6; AEC Qualified: N; VDC_V: 50V; AEC Category: Q200
R4 = CMP-0026695-1: RES, 3.30 k, 1%, 0.1 W, AEC-Q200 Grade 0, 0402; Manufacturer: Panasonic; Power_W: 100mW; TempCo: 100 ppm/C; Value_Code: 3k30; U/M: EA; Value: 3.30k; Res_ohm: 3.3k; SizeX_mm: 1; SizeY_mm: 0.5; SizeZ_mm: 0.6; Value2: 0.1W; AEC Qualified: Y; VDC_V: 50V; AEC Grade: 0; AEC Category: Q200
R6 = CMP-0026100-2: RES, 1.00 M, 1%, 0.063 W, AEC-Q200 Grade 0, 0402; Manufacturer: Vishay-Dale; Power_W: 63mW; TempCo: 100 ppm/C; Value_Code: 1M00; Value: 1.00Meg; EIA_Code: E96; Res_ohm: 1M; SizeX_mm: 1; SizeY_mm: 0.5; SizeZ_mm: 0.6; Value2: 0.063W; AEC Qualified: Y; VDC_V: 50V; AEC Category: Q200; AEC Grade: 0
R7 R8 R14 = CMP-0026825-5: RES, 10 k, 5%, 0.063 W, AEC-Q200 Grade 0, 0402; Manufacturer: Vishay-Dale; Power_W: 63mW; TempCo: 200 ppm/C; Value_Code: 10k0; Value: 10k; EIA_Code: E24; SizeX_mm: 1; SizeY_mm: 0.5; SizeZ_mm: 0.6; Value2: 0.063W; AEC Qualified: Y; VDC_V: 50V; AEC Category: Q200; AEC Grade: 0
R9-R12 R17 = CMP-0026852-3: RES, 1.0 k, 5%, 0.063 W, AEC-Q200 Grade 0, 0402; Manufacturer: Vishay-Dale; Power_W: 63mW; TempCo: 200 ppm/C; Value_Code: 1k00; Value: 1.0k; EIA_Code: E24; Res_ohm: 1k; SizeX_mm: 1; SizeY_mm: 0.5; SizeZ_mm: 0.6; Value2: 0.063W; AEC Qualified: Y; VDC_V: 50V; AEC Category: Q200; AEC Grade: 0
R13 R16 = CMP-0026824-3: RES, 100, 5%, 0.063 W, AEC-Q200 Grade 0, 0402; Manufacturer: Vishay-Dale; Power_W: 63mW; TempCo: 200 ppm/C; Value_Code: 100R; Value: 100; EIA_Code: E24; SizeX_mm: 1; SizeY_mm: 0.5; SizeZ_mm: 0.6; Value2: 0.063W; AEC Qualified: Y; VDC_V: 50V; AEC Category: Q200; AEC Grade: 0
R15 = CMP-0026413-2: RES, 4.87 k, 1%, 0.063 W, AEC-Q200 Grade 0, 0402; Manufacturer: Vishay-Dale; Power_W: 63mW; TempCo: 100 ppm/C; Value_Code: 4k87; Value: 4.87k; EIA_Code: E96; SizeX_mm: 1; SizeY_mm: 0.5; SizeZ_mm: 0.6; Value2: 0.063W; AEC Qualified: Y; VDC_V: 50V; AEC Category: Q200; AEC Grade: 0
R18 = CMP-0026946-3: RES, 51, 5%, 0.063 W, AEC-Q200 Grade 0, 0402; Manufacturer: Vishay-Dale; Power_W: 63mW; TempCo: 200 ppm/C; Value_Code: 51R0; Value: 51; EIA_Code: E24; SizeX_mm: 1; SizeY_mm: 0.5; SizeZ_mm: 0.6; Value2: 0.063W; AEC Qualified: Y; VDC_V: 50V; AEC Category: Q200; AEC Grade: 0
R19 R20 = CMP-0026934-3: RES, 470, 5%, 0.063 W, AEC-Q200 Grade 0, 0402; Manufacturer: Vishay-Dale; Power_W: 63mW; TempCo: 200 ppm/C; Value_Code: 470R; Value: 470; EIA_Code: E24; SizeX_mm: 1; SizeY_mm: 0.5; SizeZ_mm: 0.6; Value2: 0.063W; AEC Qualified: Y; VDC_V: 50V; AEC Category: Q200; AEC Grade: 0
SH-J14-SH-J20 = CMP-0003761-2: Shunt, 2.54mm, Gold, Black; Manufacturer: Wurth Elektronik
TP1-TP7 = CMP-0003825-1: 1mm Test Point, SMT; Manufacturer: Any
USB1 = CMP-0055311-1: Receptacle, USB 2.0, Micro B, 5 Position, R/A, SMT; Manufacturer: Molex; CNHeader: FALSE; Current_A: 1.8A; Gender: Female; Voltage_V: 30V; Pitch_mm: 0.65; ContactFinish: Gold; CT: TRUE; Cert_UL: Y
XDS1 = CMP-0077954-1: MSP432E401YTPDT, PDT0128A (TQFP-128); Alternate Manufacturer: Texas Instruments; SizeAreaWB_mm2: 324; SizeZ_mm: 1.2; SizeX_mm: 16; SizeArea_mm2: 256; CompType: IC; AEC Qualified: N; AEC Category: Q200
Y1 = CMP-0004635-3: Crystal, 16 MHz, 8pF, SMD; Manufacturer: NDK; TaMax_C: 70°C; TaMin_C: -10°C; Frequency Stability: +/-30ppm; Frequency_Fixed: 16MHz

## Sheet MD133_M0.SchDoc: MSPM0G3507-Q1
size 431 x 279 mm; Date: Not shown in title block; ApprovedBy: Not shown in title block; CheckedBy: Not shown in title block; Author: Not shown in title block; CompanyName: Not shown in title block; DrawnBy: Mojtaba Afshar; Engineer: Not shown in title block; Organization: Not shown in title block; Address1: Not shown in title block; Address2: Not shown in title block; Address3: Not shown in title block; Address4: Not shown in title block; DocumentNumber: 1; Revision: Use project parameter SCH_Rev; SheetNumber: 3; SheetTotal: 1; PageSetup: Record=PageOptions¦CenterHorizontal=True¦CenterVertical=True¦PrintScale=1.00¦XCorrection=1.00¦YCorrection=1.00¦PrintKind=0¦BorderSize=5000000¦LeftOffset=0¦BottomOffset=0¦Orientation=2¦PaperLength=1000¦PaperWidth=1000¦Scale=100¦PaperSource=15¦PrintQuality=600¦MediaType=1¦DitherType=10¦PaperKind=Letter¦PrintScaleMode=1
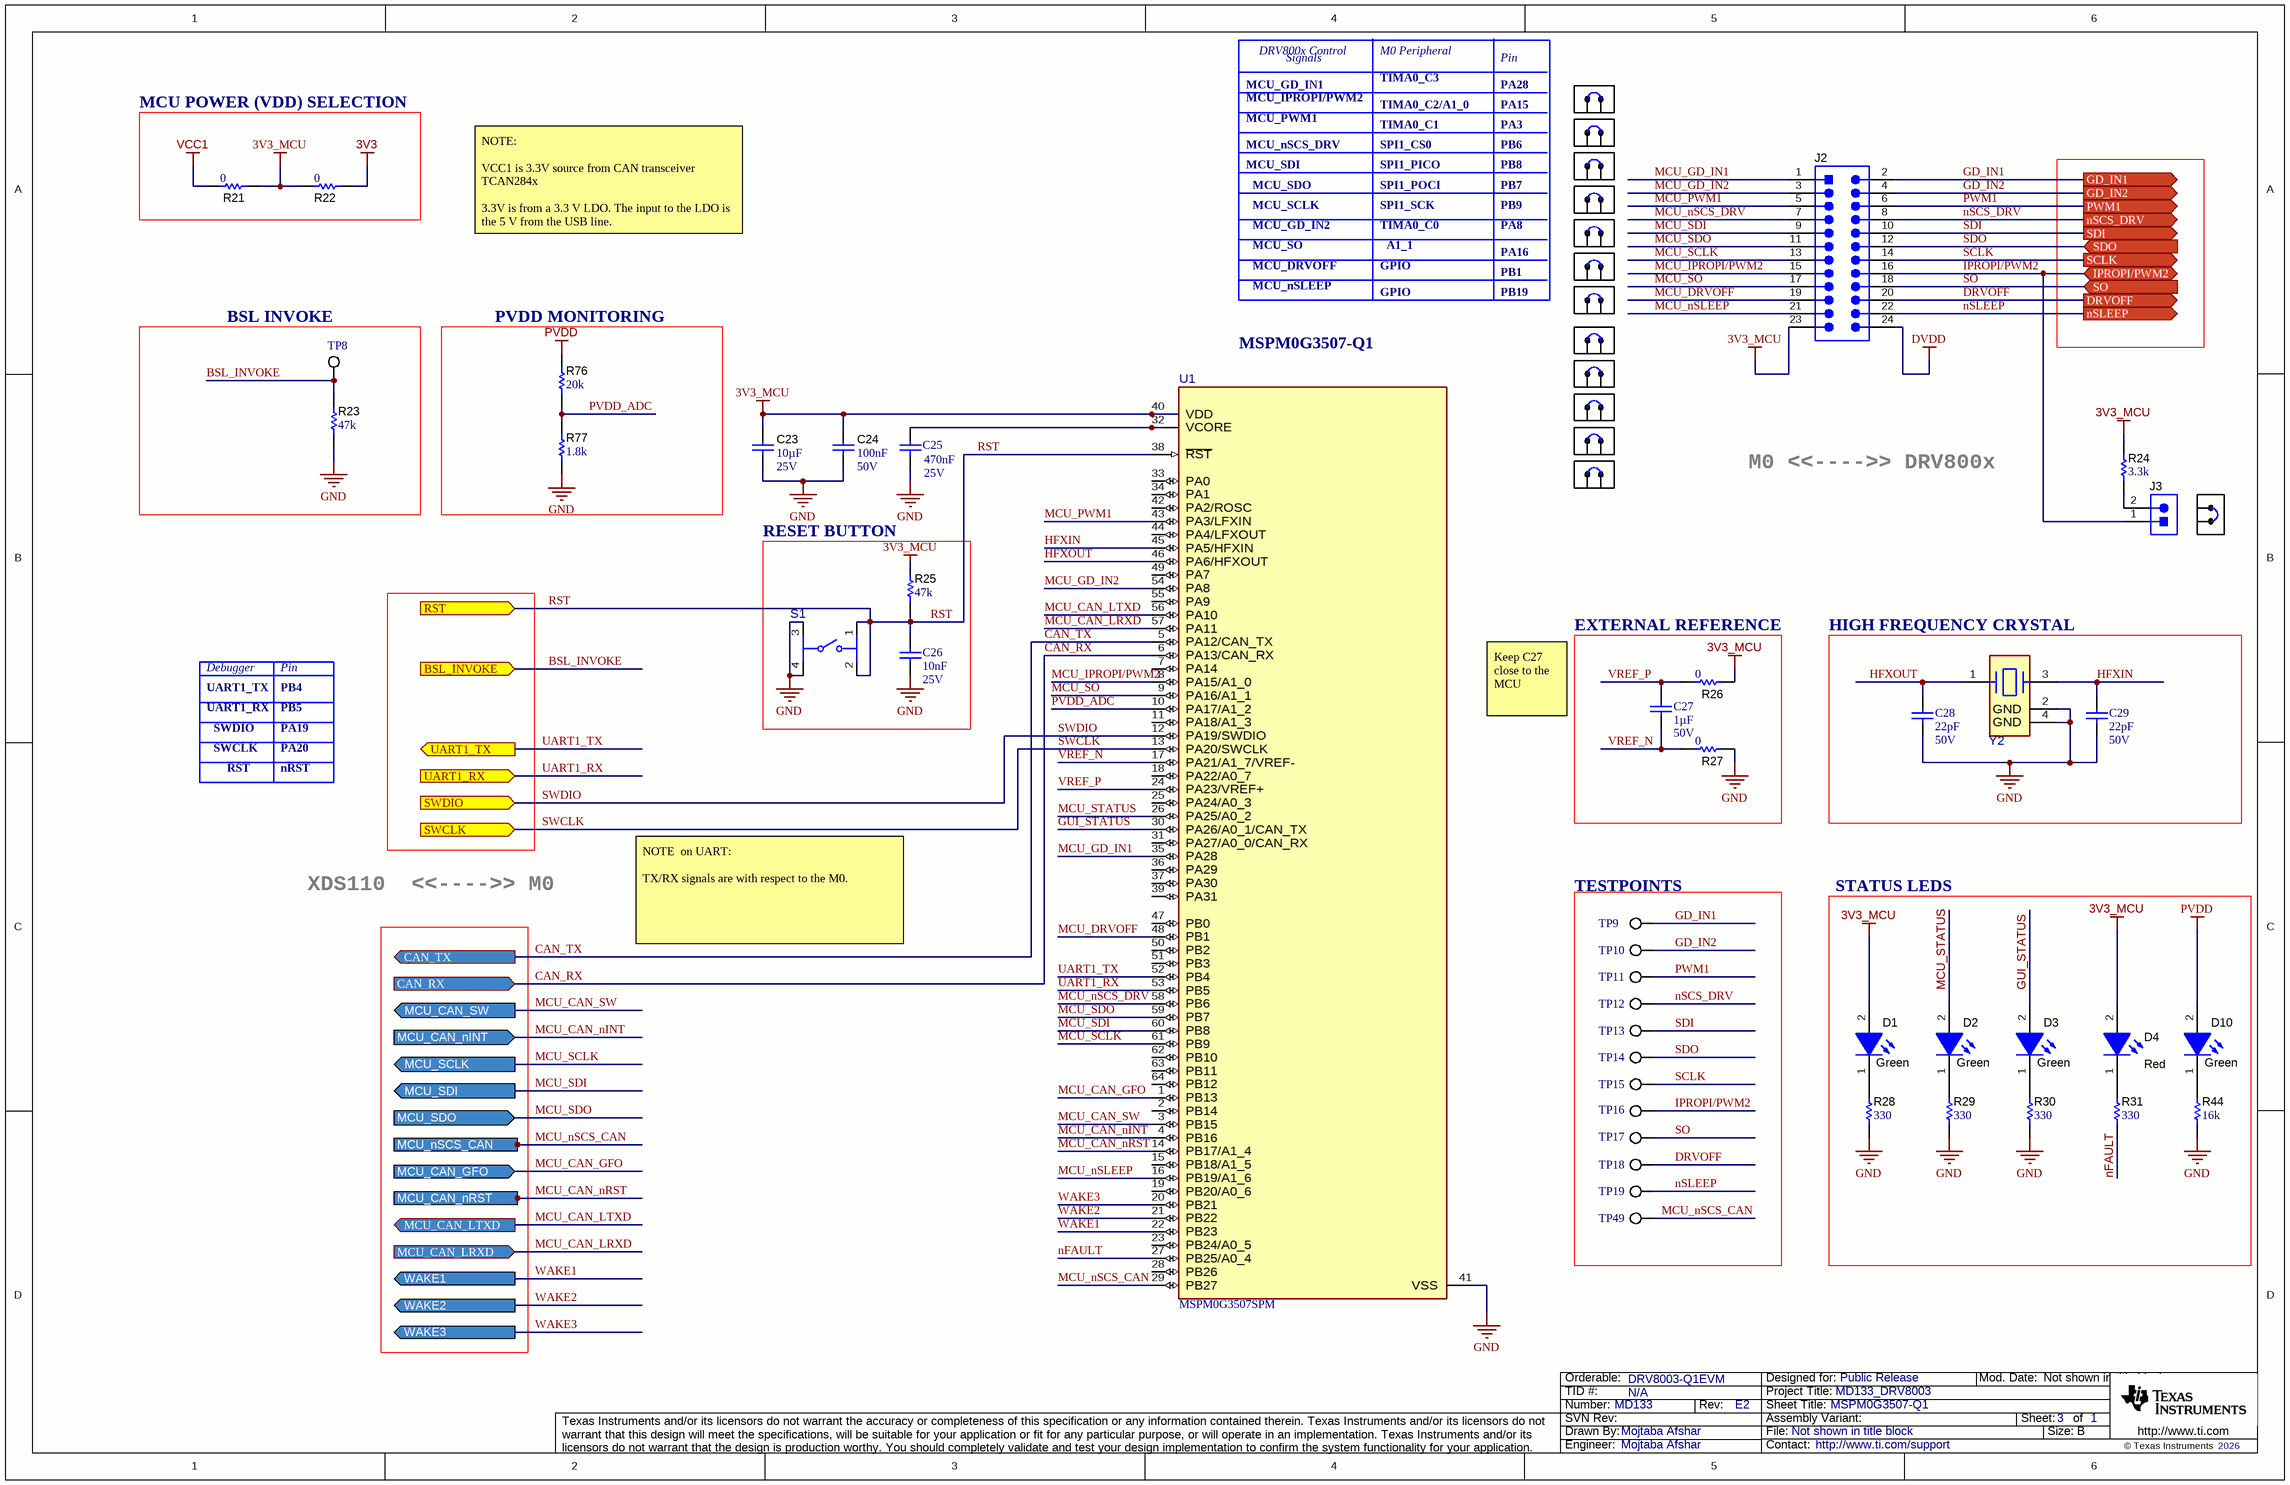
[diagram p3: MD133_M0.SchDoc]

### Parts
C23  Cap_F: 10µF  VDC_V: 25V  [0603]  (hidden comment: GRM188R61E106KA73D)
C24  Cap_F: 100nF  VDC_V: 50V  [0603]  (hidden comment: 885012206095)
C25  value 470nF  Rated Voltage (DC): 25V  [WCAP-CSGP_0603_L1.6W0.8H0.8_Reflow]  (hidden comment: 885012206075R)
C26  value 10nF  Rated Voltage (DC): 25V  [WCAP-CSGP_0603_L1.6W0.8H0.8_Reflow]  (hidden comment: 885012206065)
C27  value 1µF  Rated Voltage (DC): 50V  [WCAP-CSGP_0603_L1.6W0.8H0.8_Reflow]  (hidden comment: 885012206126)
C28  value 22pF  Rated Voltage (DC): 50V  [WCAP-CSGP_0402_L1W0.5H0.5]  (hidden comment: 885012005057)
C29  value 22pF  Rated Voltage (DC): 50V  [WCAP-CSGP_0402_L1W0.5H0.5]  (hidden comment: 885012005057)
D1  value Green  [WL-SMCW_GREEN]  (hidden comment: 150060VS75000)
D2  value Green  [WL-SMCW_GREEN]  (hidden comment: 150060VS75000)
D3  value Green  [WL-SMCW_GREEN]  (hidden comment: 150060VS75000)
D4  value Red  [WL-SMCW_RED]  (hidden comment: 150060RS75000)
D10  value Green  [WL-SMCW_GREEN]  (hidden comment: 150060VS75000)
J2  TSW-112-08-G-D  [Samtec_TSW-112-08-x-D]  (value not drawn)
J3  TSW-102-07-G-S  [TSW-102-07-G-S]  (value not drawn)
R21  value 0  [0603]  (hidden comment: Resistor)
R22  value 0  [0603]  (hidden comment: Resistor)
R23  ValueDisplayed: 47k  [0402]  (hidden comment: CRCW040247K0JNED)
R24  ValueDisplayed: 3.3k  [0603]  (hidden comment: RC0603JR-073K3L)
R25  ValueDisplayed: 47k  [0402]  (hidden comment: CRCW040247K0JNED)
R26  value 0  [0603]  (hidden comment: Resistor)
R27  value 0  [0603]  (hidden comment: Resistor)
R28  ValueDisplayed: 330  [0603]  (hidden comment: RC0603JR-07330RL)
R29  ValueDisplayed: 330  [0603]  (hidden comment: RC0603JR-07330RL)
R30  ValueDisplayed: 330  [0603]  (hidden comment: RC0603JR-07330RL)
R31  ValueDisplayed: 330  [0603]  (hidden comment: RC0603JR-07330RL)
R44  ValueDisplayed: 16k  [0603]  (hidden comment: RC0603JR-0716KL)
R76  ValueDisplayed: 20k  [0603]  (hidden comment: RC0603JR-0720KL)
R77  ValueDisplayed: 1.8k  [0603]  (hidden comment: RC0603JR-071K8L)
S1  430481025816  [FP-430481025816_SMT_SW_6MM2_6MM2-MFG]  (value not drawn)
SH-J1  60900213421  [Wurth_60900213421]  (value not drawn)
SH-J2  60900213421  [Wurth_60900213421]  (value not drawn)
SH-J3  60900213421  [Wurth_60900213421]  (value not drawn)
SH-J4  60900213421  [Wurth_60900213421]  (value not drawn)
SH-J5  60900213421  [Wurth_60900213421]  (value not drawn)
SH-J6  60900213421  [Wurth_60900213421]  (value not drawn)
SH-J7  60900213421  [Wurth_60900213421]  (value not drawn)
SH-J8  60900213421  [Wurth_60900213421]  (value not drawn)
SH-J9  60900213421  [Wurth_60900213421]  (value not drawn)
SH-J10  60900213421  [Wurth_60900213421]  (value not drawn)
SH-J11  60900213421  [Wurth_60900213421]  (value not drawn)
SH-J12  60900213421  [Wurth_60900213421]  (value not drawn)
SH-J13  60900213421  [Wurth_60900213421]  (value not drawn)
TP8  5002  [Keystone5002]  (value not drawn)
TP9  5012  [Keystone5012]  (value not drawn)
TP10  5012  [Keystone5012]  (value not drawn)
TP11  5012  [Keystone5012]  (value not drawn)
TP12  5012  [Keystone5012]  (value not drawn)
TP13  5012  [Keystone5012]  (value not drawn)
TP14  5012  [Keystone5012]  (value not drawn)
TP15  5012  [Keystone5012]  (value not drawn)
TP16  5016  [Testpoint_Keystone_Compact]  (value not drawn)
TP17  5016  [Testpoint_Keystone_Compact]  (value not drawn)
TP18  5012  [Keystone5012]  (value not drawn)
TP19  5012  [Keystone5012]  (value not drawn)
TP49  5012  [Keystone5012]  (value not drawn)
U1  MSPM0G3507SPM  [PM0064A-MFG]
Y2  X1E0000210179  [FP-X1E0000210179_TSX-3225-MFG]  (value not drawn)

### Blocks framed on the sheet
MCU POWER (VDD) SELECTION: R21 R22
BSL INVOKE: R23 TP8
PVDD MONITORING: R76 R77
RESET BUTTON: C26 R25 S1
EXTERNAL REFERENCE: C27 R26 R27
HIGH FREQUENCY CRYSTAL: C28 C29 Y2
TESTPOINTS: TP9-TP19 TP49
STATUS LEDS: D1-D4 D10 R28-R31 R44

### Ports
BSL_INVOKE (in), CAN_RX (in), CAN_TX (out), DRVOFF (out), GD_IN1 (out), GD_IN2 (out), IPROPI/PWM2 (bidir), MCU_CAN_GFO (in), MCU_CAN_LRXD (in), MCU_CAN_LTXD (out), MCU_CAN_nINT (in), MCU_CAN_nRST (out), MCU_CAN_SW (out), MCU_nSCS_CAN (out), MCU_SCLK (out), MCU_SDI (out), MCU_SDO (in), nSCS_DRV (out), nSLEEP (out), PWM1 (out), RST (in), SCLK (out), SDI (out), SDO (in), SO (in), SWCLK (in), SWDIO (in), UART1_RX (in), UART1_TX (out), WAKE1 (out), WAKE2 (out), WAKE3 (out)

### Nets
3V3: R22.1
3V3_MCU: C23.1 C24.1 D1.2(A) D4.2(A) J2.23 R21.1 R22.2 R24.2 R25.2 R26.1 U1.40(VDD)
DVDD: J2.24
GND: C23.2 C24.2 C25.1 C26.1 C28.1 C29.1 R23.1 R27.1 R28.1 R29.1 R30.1 R44.1 R77.1 S1.3 S1.4 U1.41(VSS) Y2.2(GND) Y2.4(GND)
PVDD: D10.2(A) R76.2
VCC1: R21.2
BSL_INVOKE: R23.2 TP8.1 ; port BSL_INVOKE
CAN_RX: U1.6(PA13/CAN_RX) ; port CAN_RX
CAN_TX: U1.5(PA12/CAN_TX) ; port CAN_TX
DRVOFF: J2.20 TP18.1 ; port DRVOFF
GD_IN1: J2.2 TP9.1 ; port GD_IN1
GD_IN2: J2.4 TP10.1 ; port GD_IN2
GUI_STATUS: D3.2(A) U1.30(PA26/A0_1/CAN_TX)
HFXIN: C29.2 U1.45(PA5/HFXIN) Y2.3
HFXOUT: C28.2 U1.46(PA6/HFXOUT) Y2.1
IPROPI/PWM2: J2.16 J3.1 TP16.1 ; port IPROPI/PWM2
MCU_CAN_GFO: U1.1(PB13) ; port MCU_CAN_GFO
MCU_CAN_LRXD: U1.57(PA11) ; port MCU_CAN_LRXD
MCU_CAN_LTXD: U1.56(PA10) ; port MCU_CAN_LTXD
MCU_CAN_nINT: U1.4(PB16) ; port MCU_CAN_nINT
MCU_CAN_nRST: U1.14(PB17/A1_4) ; port MCU_CAN_nRST
MCU_CAN_SW: U1.3(PB15) ; port MCU_CAN_SW
MCU_DRVOFF: J2.19 U1.48(PB1)
MCU_GD_IN1: J2.1 U1.35(PA28)
MCU_GD_IN2: J2.3 U1.54(PA8)
MCU_IPROPI/PWM2: J2.15 U1.8(PA15/A1_0)
MCU_nSCS_CAN: TP49.1 U1.29(PB27) ; port MCU_nSCS_CAN
MCU_nSCS_DRV: J2.7 U1.58(PB6)
MCU_nSLEEP: J2.21 U1.16(PB19/A1_6)
MCU_PWM1: J2.5 U1.43(PA3/LFXIN)
MCU_SCLK: J2.13 U1.61(PB9) ; port MCU_SCLK
MCU_SDI: J2.9 U1.60(PB8) ; port MCU_SDI
MCU_SDO: J2.11 U1.59(PB7) ; port MCU_SDO
MCU_SO: J2.17 U1.9(PA16/A1_1)
MCU_STATUS: D2.2(A) U1.26(PA25/A0_2)
nFAULT: R31.1 U1.27(PB25/A0_4)
nSCS_DRV: J2.8 TP12.1 ; port nSCS_DRV
nSLEEP: J2.22 TP19.1 ; port nSLEEP
PVDD_ADC: R76.1 R77.2 U1.10(PA17/A1_2)
PWM1: J2.6 TP11.1 ; port PWM1
RST: C26.2 R25.1 S1.1 S1.2 U1.38(~{RST}) ; port RST
SCLK: J2.14 TP15.1 ; port SCLK
SDI: J2.10 TP13.1 ; port SDI
SDO: J2.12 TP14.1 ; port SDO
SO: J2.18 TP17.1 ; port SO
SWCLK: U1.13(PA20/SWCLK) ; port SWCLK
SWDIO: U1.12(PA19/SWDIO) ; port SWDIO
UART1_RX: U1.53(PB5) ; port UART1_RX
UART1_TX: U1.52(PB4) ; port UART1_TX
VREF_N: C27.1 R27.2 U1.17(PA21/A1_7/VREF-)
VREF_P: C27.2 R26.2 U1.24(PA23/VREF+)
WAKE1: U1.22(PB23) ; port WAKE1
WAKE2: U1.21(PB22) ; port WAKE2
WAKE3: U1.20(PB21) ; port WAKE3
NetC25_2: C25.2 U1.32(VCORE)
NetD1_1: D1.1(K) R28.2
NetD2_1: D2.1(K) R29.2
NetD3_1: D3.1(K) R30.2
NetD4_1: D4.1(K) R31.2
NetD10_1: D10.1(K) R44.2
NetJ3_2: J3.2 R24.1

Not connected (* = marked no-connect by the designer): U1 2(PB14) 7(PA14) 11(PA18/A1_3) 15(PB18/A1_5) 18(PA22/A0_7) 19(PB20/A0_6) 23(PB24/A0_5) 25(PA24/A0_3) 28(PB26) 31(PA27/A0_0/CAN_RX) 33(PA0) 34(PA1) 36(PA29) 37(PA30) 39(PA31) 42(PA2/ROSC) 44(PA4/LFXOUT) 47(PB0) 49(PA7) 50(PB2) 51(PB3) 55(PA9) 62(PB10) 63(PB11) 64(PB12)

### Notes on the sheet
- MCU_GD_IN1
- DRV800x Control
- Signals
- M0 Peripheral
- TIMA0_C3
- Pin
- PA28
- MCU_PWM1
- MCU_nSCS_DRV
- MCU_SDI
- MCU_IPROPI/PWM2
- TIMA0_C2/A1_0
- TIMA0_C1
- SPI1_CS0
- SPI1_PICO
- PA3
- PA15
- PB8
- PB6
- NOTE:
  VCC1 is 3.3V source from CAN transceiver TCAN284x
  3.3V is from a 3.3 V LDO. The input to the LDO is the 5 V from the USB line.
- MCU_GD_IN2
- MCU_SDO
- MCU_SCLK
- TIMA0_C0
- SPI1_POCI
- SPI1_SCK
- PA8
- PB7
- PB9
- MCU_SO
- MCU_DRVOFF
- MCU_nSLEEP
- GPIO
- A1_1
- PA16
- PB19
- PB1
- MSPM0G3507-Q1
- M0 <<---->> DRV800x
- Debugger
- UART1_TX
- PB4
- UART1_RX
- SWDIO
- SWCLK
- PA19
- PA20
- PB5
- (near U1) Keep C27 close to the MCU
- RST
- nRST
- XDS110  <<---->> M0
- NOTE  on UART:
  TX/RX signals are with respect to the M0.

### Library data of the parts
C23 = CMP-0860569-1: CAP, CERM, 10 µF, 25 V,+/- 10%, X5R, 0603; Manufacturer: MuRata; TaMin_C: -55°C; Polarized: N; SizeAreaWB_mm2: 4.68; U/M: EA; Value: 10uF; TaMax_C: 85°C; SizeZ_mm: 1; SizeX_mm: 1.6; SizeY_mm: 0.8; SizeArea_mm2: 1.28; AEC Category: Q200
C24 = CMP-0006837-4: CAP, CERM, 0.1 uF, 50 V, +/- 10%, X7R, 0603; Manufacturer: Wurth Elektronik; TaMin_C: -55°C; Polarized: N; SizeAreaWB_mm2: 4.68; Value1: Unknown; U/M: EA; Value: 0.1uF; TaMax_C: 125°C; SizeZ_mm: 1; SizeX_mm: 1.6; SizeY_mm: 0.8; SizeArea_mm2: 1.28; AEC Category: Q200
C25 = CMP-0119380-1: WCAP-CSGP Multilayer Ceramic Chip Capacitor, General Purpose, size 0603, X7R Class II, 470nF, 25VDC; Manufacturer: Wurth Elektronik; Capacitance Tolerance: +/-10%; Case/Size Code: 0603; Dissipation Factor: 10%; Insulation Resistance: 1.1GOhm; Technical Reference: X7R0603474K025DFCT20000
C26 = CMP-0104705-1: WCAP-CSGP Multilayer Ceramic Chip Capacitor, General Purpose, size 0603, X7R, 10nF, 25VDC; Manufacturer: Wurth Elektronik; Capacitance Tolerance: +/-10%; Case/Size Code: 0603; Dissipation Factor: 3.5%; Insulation Resistance: 10GOhm; Technical Reference: X7R0603103K025DFCT10000
C27 = CMP-0115494-1: WCAP-CSGP Multilayer Ceramic Chip Capacitor, General Purpose, size 0603, X7R, 1µF, 50VDC; Manufacturer: Wurth Elektronik; Capacitance Tolerance: +/-10%; Case/Size Code: 0603; Dissipation Factor: 10%; Insulation Resistance: 0.5GOhm; Technical Reference: X7R0603105K050DFCT10000
C28 C29 = CMP-0050268-1: WCAP-CSGP Multilayer Ceramic Chip Capacitor, General Purpose, size 0402, NP0, 22pF, 50VDC; Manufacturer: Wurth Elektronik; Capacitance Tolerance: +/-5%; Case/Size Code: 0402; Insulation Resistance: 10GOhm; Q Factor: 840; Technical Reference: NP00402220J050DFCT10000
D1-D3 D10 = CMP-0002894-2: LED, Green, SMD; Manufacturer: Wurth Elektronik; Type: AlInGaP; Value2: 2V; Io_A: 20mA; Value1: W
D4 = CMP-0002947-3: LED, Red, SMD; Manufacturer: Wurth Elektronik; Value1: 0.072W; Vf_V: 2V; Angle: 140; Tjmax_C: 85°C; Type: AlInGaP; Vr_V: 5V; Io_A: 30mA; Power_TotalModule: 72mW
J2 = CMP-0750191-1: Header, 2.54mm, 12x2, Gold, TH; Manufacturer: Samtec; RowSpacing_mm: 2.54; Cert_UL: Y; Voltage_V: 550V; Shrouded: N; Gender: Male; Row_Count: 2
J3 = CMP-0075405-3: Header, 100mil, 2x1, Gold, TH; Manufacturer: Samtec; Pitch_mm: 2.54; Gender: Male; Cert_CSA: Y; Row_Count: 1; Cert_CULUS: N; Current_A: 6.3A; Green_Lifecycle: Active; Green_REACh: Passed; Voltage_V: 550V
R21 R22 R26 R27 = CMP-0025885-5: RES, 0, 5%, 0.1 W, 0603; PartNumber: RC0603JR-070RL; Manufacturer: Yageo; Power_W: 100mW; VDC_V: 75V; AEC Qualified: N; SizeZ_mm: 1; AEC Category: Q200; EIA_Code: E24; SizeArea_mm2: 1.28; SizeAreaWB_mm2: 4.68; SizeX_mm: 1.6; SizeY_mm: 0.8; TempCo: 200 ppm/C; Value2: 0.1W; Value_Code: 0000
R23 R25 = CMP-0026935-3: RES, 47 k, 5%, 0.063 W, AEC-Q200 Grade 0, 0402; Manufacturer: Vishay-Dale; Power_W: 63mW; TempCo: 200 ppm/C; Value_Code: 47k0; Value: 47k; EIA_Code: E24; SizeX_mm: 1; SizeY_mm: 0.5; SizeZ_mm: 0.6; Value2: 0.063W; AEC Qualified: Y; VDC_V: 50V; AEC Category: Q200; AEC Grade: 0
R24 = CMP-0025918-5: RES, 3.3 k, 5%, 0.1 W, 0603; Manufacturer: Yageo; Power_W: 100mW; TempCo: 100 ppm/C; Value_Code: 3k30; Value: 3.3k; EIA_Code: E24; SizeX_mm: 1.6; SizeY_mm: 0.8; SizeZ_mm: 1; Value2: 0.1W; SizeArea_mm2: 1.28; AEC Qualified: N; VDC_V: 75V; AEC Category: Q200; SizeAreaWB_mm2: 4.68
R28-R31 = CMP-0025912-5: RES, 330, 5%, 0.1 W, 0603; Manufacturer: Yageo; Power_W: 100mW; TempCo: 100 ppm/C; Value_Code: 330R; Value: 330; EIA_Code: E24; SizeX_mm: 1.6; SizeY_mm: 0.8; SizeZ_mm: 1; Value2: 0.1W; SizeArea_mm2: 1.28; AEC Qualified: N; VDC_V: 75V; AEC Category: Q200; SizeAreaWB_mm2: 4.68
R44 = CMP-0025891-5: RES, 16 k, 5%, 0.1 W, 0603; Manufacturer: Yageo; Power_W: 100mW; TempCo: 100 ppm/C; Value_Code: 16k0; Value: 16k; EIA_Code: E24; SizeAreaWB_mm2: 4.68; SizeX_mm: 1.6; SizeY_mm: 0.8; SizeZ_mm: 1; Value2: 0.1W; SizeArea_mm2: 1.28; AEC Qualified: N; VDC_V: 75V; AEC Category: Q200
R76 = CMP-0025900-5: RES, 20 k, 5%, 0.1 W, 0603; Manufacturer: Yageo; Power_W: 100mW; TempCo: 100 ppm/C; Value_Code: 20k0; Value: 20k; EIA_Code: E24; SizeX_mm: 1.6; SizeY_mm: 0.8; SizeZ_mm: 1; Value2: 0.1W; SizeArea_mm2: 1.28; AEC Qualified: N; VDC_V: 75V; AEC Category: Q200; SizeAreaWB_mm2: 4.68
R77 = CMP-0025898-5: RES, 1.8 k, 5%, 0.1 W, 0603; Manufacturer: Yageo; Power_W: 100mW; TempCo: 100 ppm/C; Value_Code: 1k80; Value: 1.8k; EIA_Code: E24; SizeX_mm: 1.6; SizeY_mm: 0.8; SizeZ_mm: 1; Value2: 0.1W; SizeArea_mm2: 1.28; AEC Qualified: N; VDC_V: 75V; AEC Category: Q200; SizeAreaWB_mm2: 4.68
S1 = CMP-0097347-1: Tactile Switch SPST-NO Top Actuated Surface Mount; Manufacturer: Wurth Electronics; VDC_V: 12V; Electromechanical Life: 1000000Cycles; SizeZ_mm: 2.7mm; Coil Resistance_ohm: 100mΩ; Operating Force: 160gf; AEC Qualified: No; Contact Current Rating: 50mA
SH-J1-SH-J13 = CMP-0003761-2: as SH-J14 on sheet MD133_XDS110
TP8 = CMP-0055139-2: Test Point, Miniature, White, TH; Manufacturer: Keystone Electronics; ContactFinish: Silver; Green_REACh: Passed; CT: TRUE; Green_Lifecycle: Active; CNHeader: FALSE
TP9-TP15 TP18 TP19 TP49 = CMP-0055149-2: Test Point, Multipurpose, White, TH; Manufacturer: Keystone Electronics; ContactFinish: Silver; CT: TRUE; CNHeader: FALSE; Green_Lifecycle: Active; Green_REACh: Passed
TP16 TP17 = CMP-0055153-2: Test Point, Compact, SMT; Manufacturer: Keystone Electronics; Green_Lifecycle: Active; Green_REACh: Passed; CNHeader: FALSE; CT: TRUE
U1 = CMP-0093960-1: Mixed-Signal Microcontrollers With CAN-FD Interface LQFP64; Manufacturer: Texas Instruments; Number Of I2C Channels: 2; Frequency_Fixed: 80MHz; Number Of Cores: 1; Number Of Pwm Channels: 14; Data Bus Width: 32bits; Standoff Height: 0.05mm; SizeZ_mm: 1.6mm; Number Of I/Os: 60; Memory Type: FLASH; Min Supply Voltage: 1.62V; Number Of Adc Channels: 16; Memory Size: 128KBytes; TJmax_C: +130°C; Number Of Uart Channels: 4; Number Of Timers/Counters: 7; Max Supply Voltage: 3.6V; TaMin_C: -40°C; Core Architecture: ARM Cortex-M0+; Interface: I2C,SPI,UART,CAN,LIN,IrDA,SMBus; Ram Size: 32KBytes; AEC Qualified: No; TaMax_C: +125°C
Y2 = CMP-0098168-2: Crystal 40MHz ±10ppm (Tol) ±20ppm (Stability) 12pF FUND 40Ohm 4-Pin Mini-CSMD T/R; Manufacturer: Seiko Epson; SizeZ_mm: 0.6mm; AEC Qualified: No; Esr: 40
